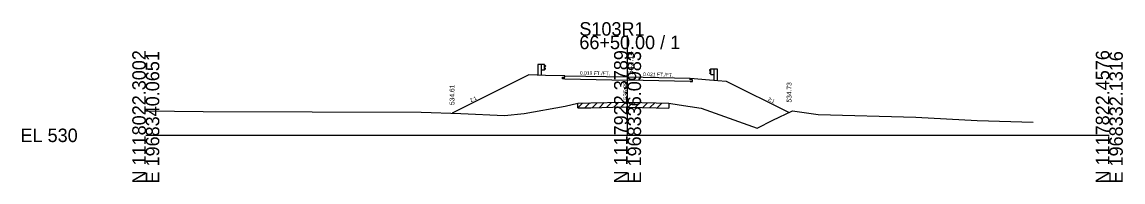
# Model space of a CAD drawing. Extents: x -26 to 203, y -10 to 12018.
# Drawn here: x -25.7 to 202.8, y 6990.3 to 7023.5 of the extents above; entities that cross this region are included whole.
import ezdxf

# ---------------------------------------------------------------- set-up
doc = ezdxf.new("R2010")
doc.units = 0
for name, color, linetype in [('Level 10', 7, 'Continuous'), ('Level 11', 7, 'Continuous'), ('Level 12', 7, 'Continuous'), ('Level 24', 7, 'Continuous'), ('Level 32', 7, 'Continuous'), ('Level 33', 7, 'Continuous'), ('Level 59', 7, 'Continuous'), ('Level 6', 7, 'Continuous'), ('Level 60', 7, 'Continuous'), ('Level 61', 7, 'Continuous'), ('Level 63', 7, 'Continuous'), ('Level 7', 7, 'Continuous')]:
    doc.layers.add(name, color=color, linetype=linetype)

msp = doc.modelspace()

# ---------------------------------------------------------------- linework, layer by layer
at = {"layer": 'Level 11'}
for p, q in [((86.5, 7012.08), (87, 7012.07)), ((86.5, 7011.72), (86.5, 7012.08)), ((87, 7011.71), (86.5, 7011.72)), ((87, 7012.07), (87, 7012.39)), ((113, 7011.56), (113, 7011.87)), ((113.5, 7011.55), (113, 7011.56)), ((113.5, 7011.19), (113.5, 7011.55)), ((113, 7011.2), (113.5, 7011.19))]:
    msp.add_line(p, q, dxfattribs=at)
at = {"layer": 'Level 12'}
for p in [(87, 7011.71), (113, 7011.2)]:
    msp.add_line(p, (100, 7011.47), dxfattribs=at)
at = {"layer": 'Level 24'}
for p, q in [((81.4, 7014.71), (81.4, 7012.51)), ((82.06, 7014.71), (81.4, 7014.71)), ((82.06, 7014.71), (82.06, 7012.49)), ((82.73, 7014.71), (82.06, 7014.71)), ((82.73, 7013.55), (82.73, 7014.71)), ((82.73, 7014.64), (83, 7014.44)), ((83, 7014.39), (82.73, 7014.19)), ((83, 7013.87), (82.73, 7014.07)), ((82.73, 7013.62), (83, 7013.82)), ((83, 7014.44), (83, 7014.39)), ((83, 7013.82), (83, 7013.87)), ((117.27, 7013.71), (117, 7013.51)), ((117.27, 7012.62), (117.27, 7013.79)), ((117.27, 7013.79), (117.94, 7013.79)), ((117.94, 7013.79), (117.94, 7011.46)), ((117.94, 7013.79), (118.6, 7013.79)), ((118.6, 7013.79), (118.6, 7011.4)), ((82.73, 7013.55), (82.06, 7013.55)), ((117, 7013.51), (117, 7013.46)), ((117, 7013.46), (117.27, 7013.26)), ((117, 7012.94), (117.27, 7013.14)), ((117, 7012.89), (117, 7012.94)), ((117.27, 7012.69), (117, 7012.89)), ((117.27, 7012.62), (117.94, 7012.62))]:
    msp.add_line(p, q, dxfattribs=at)
at = {"layer": 'Level 59'}
for p, q in [((87, 7012.39), (100, 7012.14)), ((100, 7012.14), (113, 7011.87))]:
    msp.add_line(p, q, dxfattribs=at)
at = {"layer": 'Level 6'}
for p, q in [((83, 7012.46), (79.5, 7012.57)), ((87, 7012.39), (83, 7012.46)), ((113, 7011.87), (117, 7011.54)), ((117, 7011.54), (120.5, 7011.25))]:
    msp.add_line(p, q, dxfattribs=at)
at = {"layer": 'Level 60'}
for p, q in [((92.38, 7006.74), (99.2, 7006.9)), ((99.2, 7006.9), (100, 7006.88)), ((100, 7006.88), (105.95, 7006.72)), ((0, 7005.06), (11.94, 7004.92)), ((11.94, 7004.92), (57.18, 7004.78)), ((57.18, 7004.78), (65.42, 7004.56)), ((65.42, 7004.56), (74.45, 7004.12)), ((74.45, 7004.12), (78.55, 7004.55)), ((78.55, 7004.55), (87.06, 7006.07)), ((87.06, 7006.07), (89.66, 7006.68)), ((89.66, 7006.68), (92.38, 7006.74)), ((105.95, 7006.72), (108.59, 7006.65)), ((108.59, 7006.65), (110.69, 7006.34)), ((110.69, 7006.34), (115.25, 7005.61)), ((115.25, 7005.61), (120.14, 7003.88)), ((130.17, 7003.15), (134.25, 7005.07)), ((134.25, 7005.07), (139.58, 7004.33)), ((120.14, 7003.88), (126.92, 7001.46)), ((126.92, 7001.46), (130.17, 7003.15)), ((139.58, 7004.33), (159.87, 7003.75)), ((159.87, 7003.75), (172.59, 7003.1)), ((172.59, 7003.1), (184.23, 7002.7))]:
    msp.add_line(p, q, dxfattribs=at)
at = {"layer": 'Level 61'}
for p, q in [((95.66, 7005.81), (96.68, 7006.84)), ((97.16, 7005.85), (98.18, 7006.87)), ((98.66, 7005.89), (99.66, 7006.89)), ((100.16, 7005.87), (101.13, 7006.85)), ((89.66, 7005.68), (90.68, 7006.7)), ((89.66, 7005.68), (89.66, 7006.68)), ((89.66, 7005.68), (92.38, 7005.74)), ((91.16, 7005.71), (92.18, 7006.73)), ((92.38, 7005.74), (99.2, 7005.9)), ((92.66, 7005.74), (93.68, 7006.77)), ((94.16, 7005.78), (95.18, 7006.8)), ((99.2, 7005.9), (100, 7005.88)), ((100, 7005.88), (105.95, 7005.72)), ((101.66, 7005.83), (102.63, 7006.81)), ((103.16, 7005.79), (104.13, 7006.77)), ((104.66, 7005.75), (105.63, 7006.73)), ((105.95, 7005.72), (108.59, 7005.65)), ((106.16, 7005.71), (107.13, 7006.69)), ((108.59, 7006.65), (108.59, 7005.65))]:
    msp.add_line(p, q, dxfattribs=at)
at = {"layer": 'Level 63'}
for p, q in [((100, 7000), (100, 7020.7)), ((0, 7000), (100, 7000)), ((100, 7000), (200, 7000))]:
    msp.add_line(p, q, dxfattribs=at)
at = {"layer": 'Level 7'}
for p, q in [((79.5, 7012.57), (63.57, 7004.61)), ((120.5, 7011.25), (133.53, 7004.73))]:
    msp.add_line(p, q, dxfattribs=at)

# ---------------------------------------------------------------- texts
at = {"layer": 'Level 10'}
msp.add_text(' 536.88', height=0.9, rotation=90, dxfattribs=at).set_placement((100, 7007.02))
at = {"layer": 'Level 32'}
for s, rotation, p in [('0.019 FT./FT.', 358.9113, (90.1, 7012.58)), ('0.021 FT./FT.', 358.8084, (103.22, 7012.32)), ('2:1', 26.5651, (67.5, 7006.86)), ('2:1', 333.4349, (129.04, 7007.26))]:
    msp.add_text(s, height=0.75, rotation=rotation, dxfattribs=at).set_placement(p)
at = {"layer": 'Level 33'}
for s, p in [('534.61', (64.07, 7006.3)), ('534.73', (134.03, 7006.81))]:
    msp.add_text(s, height=1, rotation=90, dxfattribs=at).set_placement(p)
at = {"layer": 'Level 59'}
msp.add_text(' 542.14', height=1.2, rotation=90, dxfattribs=at).set_placement((101.2, 7012.14))
at = {"layer": 'Level 63'}
for s, p in [('S103R1', (90, 7020.7)), ('66+50.00 / 1', (90, 7017.9)), ('EL 530', (-26, 6998.6))]:
    msp.add_text(s, height=2.8, dxfattribs=at).set_placement(p)
for s, p in [('N 1118022.3002', (0, 6990)), ('E 1968340.0651', (2.8, 6990)), ('N 1117922.3789', (100, 6990)), ('E 1968336.0983', (102.8, 6990)), ('N 1117822.4576', (200, 6990)), ('E 1968332.1316', (202.8, 6990))]:
    msp.add_text(s, height=2.8, rotation=90, dxfattribs=at).set_placement(p)

doc.saveas('drawing.dxf')
